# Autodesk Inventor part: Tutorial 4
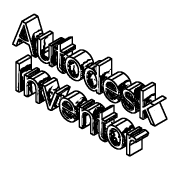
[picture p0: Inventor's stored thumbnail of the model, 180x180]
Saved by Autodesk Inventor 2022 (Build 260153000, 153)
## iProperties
Created: 2021-04
Part Number: Tutorial 4
Material: Generic
Document SubType Name: Modeling
Designer: ASUS Laptop
Density: 1 g/cm^3
Appearance: Default
Author: ASUS Laptop
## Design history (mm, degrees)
sketch "Sketch1"
  geometry: L1 (4.899, 17.404)-(34.549, 17.404); L2 (34.549, 17.404)-(34.549, 2.449); L3 (34.549, 2.449)-(4.899, 2.449); L4 (4.899, 2.449)-(4.899, 17.404); 1 further point
  constraints: 2 other
extrude "Extrusion1" new body sketch "Sketch1" distance "d0" = 2.5; taper "d1" = 0 deg
body "Solid1"
